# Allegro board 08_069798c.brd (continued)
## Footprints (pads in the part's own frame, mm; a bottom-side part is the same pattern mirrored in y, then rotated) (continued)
TSOT23_6
  rect 0.61x1.219 smd: 1(-0.95,-1.31) 2(0,-1.31) 3(0.95,-1.31) 4(0.95,1.31) 5(0,1.31) 6(-0.95,1.31)
TSOT-5
  rect 0.508x1.524 smd: 1(-0.95,-1.17) 2(0,-1.17) 3(0.95,-1.17) 4(0.95,1.17) 5(-0.95,1.17)
unnamed
  round 1.016 smd: (0,0)
YSML79W63H31_A
  rect 0.889x0.762 smd: 1(-0.65,-0.525) 2(0.65,-0.525) 3(0.65,0.525) 4(-0.65,0.525)

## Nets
5V_SUPP: C6.1 C57.1 C58.1 C61.1 C93.1 JP4.1 JP6.1 JP19.3 JP20.1 JP23.3 JP24.2(COM) R1.2(N2) R28.2(N2) R51.2(N2) R54.2(N2) R91.1 R113.2(N2) R116.2(N2) R117.1 R118.1 U25.2 U36.2 UNK5V_VDD.1
+3V3AFMC: C64.1 P3.D32 U18.8
+3V3CLK: C66.1 C104.2(N2) C124.1 C126.1 C128.1 C130.1 C131.1 C132.1 C133.1 C134.1 C143.1 R61.1 R98.2(N2) U30.6 U30.10 U30.26 U30.28 U30.32 U31.5(VOUT) Y1.4(VDD)
+3V3FMC: A2.6 A3.6 A4.6 C2.1 C44.1 C47.1 C48.1 C63.1 P3.C39 P3.D36 P3.D38 P3.D40 R19.1 R20.1 R35.1 R43.1 R44.1 R45.1 R77.1 R92.1 R93.1 R94.1 R133.1 U9.1 U9.5 U29.5
+3V3VCCO: C105.2(N2) C135.1 C139.1 C144.1 L3.2(N2) L4.2(N2) R100.2(N2) U30.16 U30.17(VVCO2) U32.5(VOUT)
+12V0FMC: C4.1 C5.1 C24.1 C25.1 C26.1 JP23.1 P3.C35 P3.C37 U37.1 U37.2 U37.3 U37.7 U38.1(VIN)
AGND: A2.2 A3.2 A4.2 A5.5 C1.2(N2) C2.2(N2) C3.2(N2) C4.2(N2) C5.2(N2) C6.2(N2) C9.2(N2) C10.2(N2) C11.2(N2) C12.2(N2) C13.2(N2) C14.2(N2) C15.1 C16.2(N2) C19.2(N2) C20.2(N2) C21.2(N2) C22.2(N2) C23.2(N2) C24.2(N2) C25.2(N2) C28.2(N2) C29.1 C30.2(N2) C31.1 C32.2(N2) C33.2(N2) C34.2(N2) C36.1 C37.2(N2) C39.1 C40.2(N2) C41.2(N2) C42.2(N2) C43.2(N2) C44.2(N2) C45.2(N2) C46.2(N2) C47.2(N2) C48.2(N2) C49.2(N2) C50.2(N2) C51.2(N2) C52.2(N2) C53.2(N2) C54.2(N2) C55.2(N2) C56.2(N2) C57.2(N2) C58.2(N2) C59.2(N2) C61.2(N2) C62.2(N2) C63.2(N2) C64.2(N2) C66.2(N2) C67.2(N2) C68.2(N2) C69.2(N2) C70.2(N2) C71.2(N2) C72.2(N2) C73.2(N2) C74.2(N2) C76.2(N2) C77.2(N2) C78.2(N2) C79.2(N2) C80.2(N2) C81.2(N2) C82.2(N2) C83.2(N2) C84.2(N2) C85.2(N2) C86.2(N2) C87.2(N2) C88.2(N2) C89.1 C90.2(N2) C91.1 C92.2(N2) C93.2(N2) C94.1 C95.2(N2) C96.1 C97.2(N2) C98.1 C99.2(N2) C100.1 C101.2(N2) C102.2(N2) C109.2(N2) C118.2(N2) C119.2(N2) C120.2(N2) C121.2(N2) C122.2(N2) C123.2(N2) C124.2(N2) C125.2(N2) C126.2(N2) C127.2(N2) C128.2(N2) C129.2(N2) C130.2(N2) C131.2(N2) C132.2(N2) C133.2(N2) C134.2(N2) C135.2(N2) C136.2(N2) C139.2(N2) C140.2(N2) C141.2(N2) C142.2(N2) C143.2(N2) C144.2(N2) CLKIN.2 CLKIN.3 CLKIN.4 CLKIN.5(SH4) CNVEN.C DS1.C INM.2 INM.3 INM.4(SH3) INP.2 INP.3 INP.4(SH3) JP3.3 JP5.3 JP7.1 JP10.3 JP11.3 JP12.3 JP13.3 JP14.1 JP15.1 JP16.1 JP21.1 JP22.1 L1.2(N2) P1.2 P1.6 P2.2 P2.6 P3.C1 P3.C4 P3.C5 P3.C8 P3.C9 P3.C12 P3.C13 P3.C16 P3.C17 P3.C20 P3.C21 P3.C24 P3.C25 P3.C28 P3.C29 P3.C32 P3.C33 P3.C36 P3.C38 P3.C40 P3.D2 P3.D3 P3.D6 P3.D7 P3.D10 P3.D13 P3.D16 P3.D19 P3.D22 P3.D25 P3.D28 P3.D37 P3.D39 P3.G1 P3.G4 P3.G5 P3.G8 P3.G11 P3.G14 P3.G17 P3.G20 P3.G23 P3.G26 P3.G29 P3.G32 P3.G35 P3.G38 P3.G40 P3.H2 P3.H3 P3.H6 P3.H9 P3.H12 P3.H15 P3.H18 P3.H21 P3.H24 P3.H27 P3.H30 P3.H33 P3.H36 P3.H39 P4.2 P4.4 P4.6(N6) P5.1 P7.11 P7.12(N6) P8.2 P8.4(N4) P11.2(N2) P12.1 R2.2(N2) R3.2(N2) R38.1 R42.2(N2) R62.2(N2) R67.1 R73.2(N2) R75.2(N2) R86.2(N2) R95.2(N2) R96.2(N2) R97.2(N2) R99.1 R101.1 R107.2(N2) R108.2(N2) R112.2(N2) R121.2(N2) R124.2(N2) R126.2(N2) R130.2(N2) R131.2(N2) R134.2(N2) R135.2(N2) R136.2(N2) R139.2(N2) R148.2(N2) R152.2(N2) S1.1A S1.2A S1.3A T1.4 TP1.1(N1) TP2.1(N1) TP3.1(N1) TP4.1(N1) U4.2 U4.5 U5.2 U5.5 U6.2 U6.5 U7.2 U7.5 U8.B1 U8.B2 U8.B6 U8.C1 U8.C2 U8.C3 U8.C4 U8.C5 U8.D3 U8.D4 U8.D5 U8.E3 U8.E4 U8.E5 U8.F5 U8.F6 U8.G5 U9.2 U11.2 U12.2 U13.2 U14.2 U15.2 U16.2 U17.2 U18.3 U18.4 U18.7(WC_N) U19.1 U19.4 U20.PAD U21.9 U21.PAD U23.3 U24.3 U25.3 U25.4 U25.5 U25.8 U26.3 U27.3 U28.3 U29.1 U29.3 U30.8 U30.9 U30.11 U30.18 U30.21 U30.27 U30.31 U30.PAD U31.2 U32.2 U33.9 U33.PAD U34.9 U34.PAD U35.9 U35.PAD U36.4 U37.9 U37.PAD U38.9 Y1.2
AVDD11: A2.3(VIN) P9.1 R36.1 U8.A1 U8.A2
DVDD11: R36.2(N2) R37.1 U8.A3
V11_OK: A2.4 A3.4 R47.2(N2) U24.1
VDD_REFBUF: C9.1 R1.1 U39.6
VDDAFE_U1: C88.1 R113.1 U1.6
VDDAFE_U2: C90.1 R28.1 U2.6
VDDCR11: P9.2(N2) R23.2(N2) R90.2(N2) VDD_11.1(N1)
VDDDRV_A1: A1.7(VS_POS) C95.1 R117.2(N2)
VDDDRV_A6: A6.7(VS_POS) C97.1 R118.2(N2)
VDDIO11: C1.1 C52.1 C53.1 C54.1 C59.1 C74.1 C76.1 C77.1 C78.1 C84.1 C85.1 IOVDD.1(N1) P10.1 R22.2(N2) R83.2(N2) U4.6(VCCB) U5.6(VCCB) U6.6(VCCB) U7.6(VCCB) U11.6(VCCB) U12.6(VCCB) U13.6(VCCB) U14.6(VCCB) U15.6(VCCB) U16.6(VCCB) U17.6(VCCB)
VDDLDO: C99.1 P6.2(N2) U8.B3 VDDLDO.1(N1)
VINN: INM.1 P1.7(N7) R3.1 R6.1 R106.1 TINM.1(N1)
VINP: INP.1 P1.1 R2.1 R4.1 R52.1 TINP.1(N1)
VSS_REFBUF: R152.1 U39.2
VSSAFE: C94.2(N2) JP3.1 JP5.1 JP19.1 JP20.3 JP21.3 JP22.3 JP25.2(COM) R26.2(N2) R27.2(N2) R115.2(N2) R128.1 R129.1 S1.4A U3.PAD VSS2V5.1(N1)
VSSAFE_U1: C89.2(N2) R26.1 U1.2(V-)
VSSAFE_U2: C91.2(N2) R27.1 U2.2(V-)
VSSDRV_A1: A1.4 A1.5 C96.2(N2) R128.2(N2)
VSSDRV_A6: A6.4 A6.5 C98.2(N2) R129.2(N2)
AD9508_RESET_N: U9.4 U20.18
AD9508_S4: R72.2(N2) R73.1 U20.9
AD9508_S5: R74.2(N2) R75.1 U20.10
AD9508_SYNC: P3.C10 U20.20 U29.2
ADCIN+: R31.1 R32.1 R70.2(N2)
ADCIN-: R76.2(N2) R88.1 R89.1
ADF435X_LOCK: P3.C23 R123.2(N2)
AUXIN+: C38.2(N2) C39.2(N2) R31.2(N2) U8.D2
AUXIN-: C38.1 C40.1 R89.2(N2) U8.E2
CLK25M: U30.29 Y1.3
CLK_N: P3.D9 RTCLK.1 U8.A7 U20.17
CLK_P: P3.D8 RTCLK.2(N2) U8.B7 U20.16
CLK_PWR_SRC: C141.1 C142.1 JP23.2(COM) U31.1 U32.1
CLK_SRCM: C138.2(N2) R68.2(N2) R69.1 U20.22
CLK_SRCP: C137.2(N2) R65.2(N2) R69.2(N2) U20.21
CLKCOM: C121.1 C123.1 U30.23
CLKIN_AUX: C65.1 CLKIN.1 R62.1
CMSRC: JP8.2(COM) U8.G2
CNV_N: R38.2(N2) R40.1 RTCNV.2(N2) U8.A5 U20.12
CNV_P: R39.1 RTCNV.1 U8.A4 U20.11
CPO: C125.1 R120.2(N2) U30.7
CS1_0: P3.C19 U20.1
CS1_1: P3.C22 U30.3
CS_N_SRC: P3.G12 R109.1 U11.3
CSB: R109.2(N2) U8.G1 U11.4
DA_N: JP11.1 P3.H8 U8.D7
DA_P: JP10.1 P3.H7 U8.C7
DB_N: JP13.1 P3.G10 U8.D6
DB_P: JP12.1 P3.G9 U8.C6
DCO_N: P3.H5 U8.B4
DCO_P: P3.H4 U8.B5
DOA: JP10.2(COM) U4.4
DOA_FMC: P3.D20 U4.3
DOB: JP11.2(COM) U5.4
DOB_FMC: P3.D21 U5.3
DOC: JP12.2(COM) U6.4
DOC_FMC: P3.G18 U6.3
DOD: JP13.2(COM) U7.4
DOD_FMC: P3.G19 U7.3
EC0: C70.1 U20.5
EC1: C69.1 U20.14
EN1V1: P5.2(N2) R20.2(N2) U35.4
EN_AFE: P2.4 U3.12 U23.4(Y) U25.1 U26.2 U27.2 U28.1 U36.3 U39.5
EN_PSU: P3.H19 R133.2(N2) U19.3 U38.2
EN_V33: U21.4 U24.4(Y)
EN_VDDLDO: P12.2(N2) R19.2(N2) U33.4
ENS1N: U2.5 U27.4(Y)
ENS1P: U1.5 U26.4(Y)
ENS3: A1.8 A6.8 U28.4(Y)
ENVIO: R35.2(N2) U34.4
EXT_5V: C101.1 JP24.1 P8.1
EXT_M2V5: C34.1 JP25.1 P8.3
EXT_VDD1V1: P4.5 R81.1 R90.1
EXT_VDD3V3: P11.1 R34.1 R82.1
EXT_VDDLDO: P4.3 R80.1 R84.1
EXT_VIO1V1: P4.1 R79.1 R83.1
FDA5: JP4.2(COM) R125.1 U3.5
FDA8: JP6.2(COM) R127.1 U3.8
FDA13: JP5.2(COM) R126.1 U3.13
FDA16: JP3.2(COM) R124.1 U3.16
FDA_OB_N: R102.1 U3.11
FDA_OB_P: R103.1 U3.10
FDA_ON: C75.1 JP15.3 JP17.1 P2.1 R33.2(N2) R102.2(N2)
FDA_OP: C75.2(N2) JP16.3 JP18.1 P2.7(N7) R18.2(N2) R103.2(N2)
FFB: C122.1 R119.2(N2) R122.1
FMC_VADJ: C3.1 C49.1 C50.1 C51.1 C55.1 C56.1 C62.1 C68.1 C71.1 C72.1 C73.1 C80.1 C81.1 C82.1 C83.1 P3.G39 P3.H40 P7.1 R16.1 R46.1 R47.1 R53.1 R55.1 R56.1 R71.1 R72.1 R74.1 U4.1 U5.1 U6.1 U7.1 U9.6(VCCB) U11.1 U11.5 U12.1 U12.5 U13.1 U13.5 U14.1 U15.1 U16.1 U17.1 U20.6 U20.13(VDD_2) U23.5 U24.5 U26.5 U27.5 U28.5
FPGACLK_N: P3.G3 U20.3
FPGACLK_P: P3.G2 U20.2
GA0: P3.C34 U18.2
GA1: P3.D35 U18.1
GP0_DIR: P3.H16 U14.5
GP1_DIR: P3.C15 U15.5
GP2_DIR: P3.G15 U16.5
GP3_DIR: P3.H17 U17.5
GPIO0: U8.G7 U14.4
GPIO0_FMC: P3.H13 U14.3
GPIO1: U8.E6 U15.4
GPIO1_FMC: P3.C11 U15.3
GPIO2: U8.F1 U16.4
GPIO2_FMC: P3.D14 U16.3
GPIO3: U8.F2 U17.4
GPIO3_FMC: P3.D15 U17.3
IN+: C35.2(N2) C36.2(N2) R32.2(N2) U8.D1
IN-: C35.1 C37.1 R88.2(N2) U8.E1
IOVDD: A3.3(VIN) P10.2(N2) R37.2(N2) U8.A6
LDO_IN_VDD1V1: C13.1 R81.2(N2) R93.2(N2) U35.1 U35.2 U35.3 U35.7
LDO_IN_VDD3V3: C10.1 R34.2(N2) R91.2(N2) U21.1 U21.2 U21.3 U21.7
LDO_IN_VDDLDO: C11.1 R80.2(N2) R92.2(N2) U33.1 U33.2 U33.3 U33.7
LDO_IN_VIO1V1: C12.1 R79.2(N2) R94.2(N2) U34.1 U34.2 U34.3 U34.7
NEG_5V0: C26.2(N2) C27.2(N2) C29.2(N2) C118.1 R137.2(N2) R138.2(N2) U19.2 U38.12 U38.PAD
OSC_EN: P3.G16 R61.2(N2) U30.4 Y1.1
OUT_VDDLDO: P6.1 R21.2(N2) R84.2(N2)
P1N: R55.2(N2) S1.2B U27.1
P1P: R53.2(N2) S1.1B(N8) U26.1
P1S1: JP19.2(COM) P1.3
P1S2: JP20.2(COM) P1.5
P3: R56.2(N2) S1.3B U28.2
PAD_A1: A1.PAD JP21.2(COM)
PAD_A6: A6.PAD JP22.2(COM)
PBIO<0>: P3.H23 P7.2
PBIO<1>: P3.G21 P7.3
PBIO<2>: P3.G22 P7.4
PBIO<3>: P3.H25 P7.5
PBIO<4>: P3.H26 P7.6
PBIO<5>: P3.G24 P7.7
PBIO<6>: P3.G25 P7.8
PBIO<7>: P3.D23 P7.9
PBIO<8>: P3.D24 P7.10
PD_V33B: P3.H22 R16.2(N2) U23.2 U24.2
PG_C2M: A2.1 A4.1 P3.D1 R24.1 R43.2(N2) R44.2(N2) U31.3 U32.3
PMSEL: JP4.3 R54.1 R125.2(N2) S1.4B
PWRGD: A4.4 P3.H20 R46.2(N2) R85.1 U9.3 U23.1
REF: C41.1 C42.1 C43.1 JP2.2(COM) JP6.3 R127.2(N2) REF.1(N1) U8.F4 U8.G4
REF3P: C30.1 R147.1 U25.6(VOUT_S) U25.7
REF3S: R146.1 U36.6(VOUT)
REFBUF_IN: JP1.3 R148.1 R149.1
REFBUF_OUT: JP2.1 R151.2(N2)
REFCLK: C127.1 C129.1 U30.24
S1_OM: C32.1 R11.1 R18.1 R106.2(N2) R114.2(N2)
S1_OP: C31.2(N2) R10.1 R33.1 R52.2(N2) R66.2(N2)
SCK: R111.2(N2) U8.E7 U13.4
SCL: P3.C30 U18.6
SCLK1: P3.D18 U20.19 U30.1
SCLK_SRC: P3.H14 R111.1 U13.3
SDA: P3.C31 U18.5
SDI: R110.2(N2) U8.F7(SDI) U12.4
SDIN1: P3.C18 U20.24 U30.2
SDIO_SRC: P3.G13 R110.1 U12.3
SDO_1: P3.D17 U20.4
SNS33: R41.1 R82.2(N2) R132.2(N2) U8.F3 U8.G3 VDD33.1(N1)
TMPC: C136.1 C140.1 U30.19
UNNAMED_4_CMOSNC7SZ125_I71_Y: R60.1 U29.4(Y)
UNNAMED_4_CN160PCDGHV2_I72_TDI: P3.D30 P3.D31
UNNAMED_4_CN160PCDGHV2_I97_LA00NCC: P3.G7 R40.2(N2)
UNNAMED_4_CN160PCDGHV2_I97_LA00PCC: P3.G6 R39.2(N2)
UNNAMED_4_DIOLED_I76_P: CNVEN.A(P) R60.2(N2)
UNNAMED_5_ADM108X_I2_ENIN: A3.1 R45.2(N2)
UNNAMED_5_ADM108X_I19_VIN: A4.3(VIN) R41.2(N2) R42.1
UNNAMED_5_DIOLED_I115_P: DS1.A(P) R85.2(N2)
UNNAMED_7_AD9508_I87_INSEL: R71.2(N2) U20.23
UNNAMED_7_ADF435X_I58_MUXOUT: R123.1 U30.30
UNNAMED_7_ADF435X_I58_RFOUTA: C138.1 L4.1 U30.13
UNNAMED_7_ADF435X_I58_RFOUTA_1: C137.1 L3.1 U30.12
UNNAMED_7_ADF435X_I58_RSET: R121.1 U30.22
UNNAMED_7_ADF435X_I58_SW: R122.2(N2) U30.5
UNNAMED_7_ADP7118V2_I90_SENSE: C105.1 R100.1 R101.2(N2) U32.4
UNNAMED_7_ADP7118V2_I95_SENSE: C104.1 R98.1 R99.2(N2) U31.4
UNNAMED_7_CAP_I6_N2: C65.2(N2) T1.5(N4)
UNNAMED_7_RES_I8_N1: R64.2(N2) R68.1 T1.3
UNNAMED_7_RES_I10_N1: R63.1 R65.1 T1.1
UNNAMED_7_RES_I10_N2: R63.2(N2) R64.1
UNNAMED_8_ADA4899_I108_FEEDBACK: A1.1 R17.2(N2)
UNNAMED_8_ADA4899_I108_INV: A1.2 R17.1
UNNAMED_8_ADA4899_I108_NINV: A1.3 R58.2(N2)
UNNAMED_8_ADA4899_I108_VOUT: A1.6 R105.1
UNNAMED_8_ADA4899_I113_FEEDBACK: A6.1 R57.2(N2)
UNNAMED_8_ADA4899_I113_INV: A6.2 R57.1
UNNAMED_8_ADA4899_I113_NINV: A6.3 R59.2(N2)
UNNAMED_8_ADA4899_I113_VOUT: A6.6 R104.1
UNNAMED_8_ADA49451_I81_: C18.2(N2) R15.2(N2) U3.4
UNNAMED_8_ADA49451_I81__1: C17.2(N2) R14.2(N2) U3.1
UNNAMED_8_ADA49451_I81__2: C18.1 R13.2(N2) U3.3
UNNAMED_8_ADA49451_I81__3: C17.1 R12.2(N2) U3.2
UNNAMED_8_ADA49451_I81__4: C19.1 R115.1 U3.14 U3.15
UNNAMED_8_ADA49451_I81__5: C20.1 R116.1 U3.6 U3.7
UNNAMED_8_ADLT6236_I15_: C79.1 R6.2(N2) U2.3
UNNAMED_8_ADLT6236_I15__1: C8.1 R7.2(N2) R9.1 U2.4
UNNAMED_8_ADLT6236_I15_OUT: C8.2(N2) R9.2(N2) R114.1 U2.1
UNNAMED_8_ADLT6236_I33_: C67.1 R4.2(N2) U1.3
UNNAMED_8_ADLT6236_I33__1: C7.1 R5.2(N2) R8.1 U1.4
UNNAMED_8_ADLT6236_I33_OUT: C7.2(N2) R8.2(N2) R66.1 U1.1
UNNAMED_8_CAP_I54_N1: C16.1 C103.2(N2) R11.2(N2) R13.1 R15.1
UNNAMED_8_CAP_I57_N2: C15.2(N2) C103.1 R10.2(N2) R12.1 R14.1
UNNAMED_8_CAP_I93_N1: C109.1 JP15.2(COM) R58.1
UNNAMED_8_CAP_I115_N1: C92.1 JP16.2(COM) R59.1
UNNAMED_8_OFFPAGE_I160_A: R30.2(N2)
UNNAMED_8_RES_I10_N1: R5.1 R29.2(N2)
UNNAMED_8_RES_I20_N1: R7.1 R78.1
UNNAMED_8_RES_I20_N2: JP14.2(COM) R78.2(N2)
UNNAMED_8_RES_I163_N1: JP17.2(COM) R70.1
UNNAMED_8_RES_I164_N1: JP18.2(COM) R76.1
UNNAMED_8_RES_I185_N2: JP17.3 R105.2(N2)
UNNAMED_8_RES_I186_N2: JP18.3 R104.2(N2)
UNNAMED_8_RES_I219_N1: JP7.2(COM) R29.1
UNNAMED_11_CAP_I205_N1: C14.1 R132.1 U21.10 U21.11 U21.12
UNNAMED_11_CAP_I213_N1: C21.1 R21.1 U33.10 U33.11 U33.12
UNNAMED_11_CAP_I221_N1: C23.1 R23.1 U35.10 U35.11 U35.12
UNNAMED_11_CAP_I227_N1: C22.1 R22.1 U34.10 U34.11 U34.12
UNNAMED_11_LINLT3045_I202_ILIM: R108.1 U21.6
UNNAMED_11_LINLT3045_I202_SET: C46.1 R95.1 U21.8(SET)
UNNAMED_11_LINLT3045_I215_ILIM: R112.1 U33.6
UNNAMED_11_LINLT3045_I215_SET: C86.1 R96.1 U33.8(SET)
UNNAMED_11_LINLT3045_I220_ILIM: R131.1 U35.6
UNNAMED_11_LINLT3045_I220_SET: C87.1 R107.1 U35.8(SET)
UNNAMED_11_LINLT3045_I229_ILIM: R130.1 U34.6
UNNAMED_11_LINLT3045_I229_SET: C45.1 R97.1 U34.8(SET)
UNNAMED_12_ADLT8604_I100_FB: R138.1 R139.1 U38.5
UNNAMED_12_ADLT8604_I100_RT: R137.1 U38.8
UNNAMED_12_ADLT8604_I100_SW: L1.1 U38.10
UNNAMED_12_ADLT8604_I100_SYNC: R136.1 U38.7
UNNAMED_12_ADLT8604_I100_TR: C27.1 U38.6
UNNAMED_12_ADP7182V3_I25_VOUT: C119.1 JP25.3 U19.5(VOUT)
UNNAMED_12_CAP_I88_N1: C28.1 JP24.3 U37.10 U37.11 U37.12
UNNAMED_12_LINLT3045_I87_EN: R24.2(N2) R77.2(N2) U37.4
UNNAMED_12_LINLT3045_I87_ILIM: R135.1 U37.6
UNNAMED_12_LINLT3045_I87_SET: C102.1 R134.1 U37.8(SET)
UNNAMED_13_ADA48072_I2_INV: A5.6 A5.7
UNNAMED_13_ADA48072_I13_INV: A5.2 C60.1 R49.1
UNNAMED_13_ADA48072_I13_NINV: A5.3 R48.2(N2)
UNNAMED_13_ADA48072_I13_OUT: A5.1 C60.2(N2) R50.1
UNNAMED_13_ADA48072_I20_VS: A5.8 R51.1
UNNAMED_13_ADA48072_I20_VS_1: A5.4(VS-) R67.2(N2)
UNNAMED_13_ADA48971_I40_: R149.2(N2) U39.3
UNNAMED_13_ADA48971_I40__1: R150.1 U39.4
UNNAMED_13_ADA48971_I40_OUT: R150.2(N2) R151.1 U39.1(OUT)
UNNAMED_13_RES_I12_N1: JP8.3 R48.1 R86.1
UNNAMED_13_RES_I17_N2: R49.2(N2) R50.2(N2) R87.1
UNNAMED_13_RES_I28_N2: JP9.3 R87.2(N2)
UNNAMED_13_RES_I29_N2: JP1.2(COM) R146.2(N2) R147.2(N2)
UNNAMED_13_RESJMPR3P_I53_B: JP1.1 JP2.3
UNNAMED_13_RESJMPRSHRT3P_I11_A: JP8.1 JP9.1
VOCM: C33.1 C100.2(N2) JP7.3 JP9.2(COM) JP14.3 P1.4 R30.1 U3.9(VOCM) VOCM.1(N1)
VTIN: C120.1 R119.1 R120.1 U30.20

Pads without a net: A2 5; A3 5; A4 5; P2 3 5; P3 C2 C3 C6 C7 C14 C26 C27 D4 D5 D11 D12 D26 D27 D29 D33 D34 G27 G28 G30 G31 G33 G34 G36 G37 H1 H10 H11 H28 H29 H31 H32 H34 H35 H37 H38; T1 2; U8 G6; U20 7 8 15; U21 5; U30 14 15 25; U33 5; U34 5; U35 5; U36 1 5 7 8; U37 5; U38 3 4 11

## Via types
v1: diameter 0.508, hole 0.254, TOP to BOTTOM, 1140 vias
v2: diameter 0.457, hole 0.152, TOP to BOTTOM, 33 vias
v3: diameter 0.711, hole 0.356, TOP to BOTTOM, 36 vias

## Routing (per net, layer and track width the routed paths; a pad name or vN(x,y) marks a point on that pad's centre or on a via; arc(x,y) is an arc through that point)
5V_SUPP: length 48.1
  TOP w0.305: 56.19,18.72 R91.1
  TOP w0.508: v2(88.82,51.17) 88.82,50.53 JP23.3 ; v1(51.54,4.3) 50.68,4.3 C61.1 R51.2 ; R54.2 v1(23.6,12.89)
  L3_PRIMARY_POWER w0.508: UNK5V_VDD.1 27.68,22.1 ; UNK5V_VDD.1 27.68,20.42 ; UNK5V_VDD.1 26,20.42 ; UNK5V_VDD.1 26,22.1
  BOTTOM w0.305: v2(88.82,51.17) 86.85,49.2 82.6,49.2 81.64,48.25 80.63,48.25 79.8,47.42 76.94,47.42 75.93,46.4 66.15,46.4 64.56,44.82 60.94,44.82 v1(58.99,42.86)
  BOTTOM w0.508: JP24.2 28.27,18.56 v1(28.27,19.19) ; JP20.1 v1(13.07,31.38) ; JP19.3 v1(13.07,34.66) ; JP6.1 v1(38.93,26.4) ; JP4.1 v1(33.88,26.4)
  vias: v1(22.73,36.89) v1(22.73,36.26) v1(22.74,21.53) v1(22.74,20.89) v1(23.36,36.89) v1(23.35,36.24) v1(23.38,21.53) v1(23.36,20.88) v1(35.62,26.86) v1(35.62,26.35) v1(36.13,26.86) v1(36.13,26.35) v1(57.02,19.05) v1(57.02,18.35) v1(57.65,19.05) v1(57.65,18.35) v1(58.48,42.86) v1(58.48,42.35) v1(58.48,28.58) v1(58.48,28.07) v1(58.99,42.35) v1(58.99,28.58) v1(58.99,28.07) v1(63.69,18.25) v1(63.69,17.74) v1(63.69,11.46) v1(63.69,10.95) v1(64.19,18.25) v1(64.19,17.74) v1(64.19,11.46) v1(64.19,10.95) v1(72.7,22.89) v1(72.7,22.38) v1(73.21,22.89) v1(73.21,22.38)
+3V3AFMC: length 11
  TOP w0.254: U18.8 91.5,18.67 90.26,18.67 C64.1
  TOP w0.508: U18.8 91.75,17.78 92.26,17.27 96.36,17.27 96.87,17.78 v1(96.87,19.54)
  BOTTOM w0.508: P3.D32 v1(96.87,19.54)
+3V3CLK: length 10.8
  TOP w0.178: v1(61.5,51.48) 61.2,51.79 U30.6 ; U30.28 57.99,55.69 57.59,55.69 57.26,56.02 ; U30.10 63.23,54.19 63.25,54.17 63.53,54.17 63.81,53.88 63.81,53.51 64.39,52.93 C126.1 64.39,52.27 64.41,52.25 C128.1 64.41,51.63 64.51,51.53 v1(64.51,51.03)
  BOTTOM w0.178: v1(64.51,51.03) v1(64.51,50.42) 63.84,50.42 C66.1 C132.1 62.22,50.77 v1(61.5,51.48)
  vias: v1(54.6,56.58) v1(54.6,56.07) v1(54.73,52.51) v1(54.73,51.94) v1(58.08,62.6) v1(59.14,63.44) v1(59.16,62.6) v1(60.24,63.42) v1(60.24,62.6) v1(79.75,57.6) v1(79.74,57.01) v1(79.74,56.44)
+3V3FMC: length 68.1
  TOP w0.254: v1(83.61,16.88) 83.61,17.38 81.07,19.92 79.99,19.92 78.91,21 78.91,28.69 78.09,29.51 78.09,31.86 78.85,32.62 78.85,33 78.86,33.02 78.86,34.9 77.52,36.24 77.52,41.77 C2.1 ; v1(101.09,45.43) 101.09,45.43 C63.1 101.09,46.04 U29.5 ; A3.6 80.32,11.93 80.41,11.84 C48.1 ; A2.6 C47.1
  TOP w0.305: v1(49.26,3.22) 49.26,7.54 v1(46.59,10.21) ; v1(43.48,12.24) 43.48,13.96 v1(42.34,15.1) ; C2.1 U9.1
  TOP w0.381: A4.6 C44.1 ; U9.5 78.29,44.51 77.64,43.86 U9.1
  TOP w0.508: v1(81.71,4.56) 80.86,4.56 C44.1 ; R45.1 C48.1 80.44,11.23 v1(80.44,10.46) ; 13.76,49.59 R20.1 13.14,50.16 ; 27.17,49.97 R19.1 27.8,49.4 ; R43.1 82.73,3.54 v1(83.55,3.54) ; v1(76.37,10.53) 76.37,11.25 C47.1 R44.1 ; 41.77,49.33 R35.1 41.14,49.9
  L3_PRIMARY_POWER w0.305: v1(43.48,12.24) 44.24,11.48 45.32,11.48 v1(46.59,10.21)
  BOTTOM w0.254: v1(83.61,16.88) R133.1 ; R77.1 41.57,15.1 v1(42.34,15.1)
  BOTTOM w0.508: P3.C39 v1(98.14,10.65) ; P3.D40 v1(96.87,9.38) ; P3.D36 v1(96.87,14.46) ; P3.D38 v1(96.87,11.92)
  vias: v1(11.81,50.23) v1(11.81,49.53) v1(12.44,50.23) v1(12.44,49.53) v1(25.84,50.16) v1(25.84,49.47) v1(26.47,50.16) v1(26.47,49.47) v1(39.62,50.29) v1(39.62,49.59) v1(40.25,50.29) v1(40.25,49.59)
+3V3VCCO: length 1.6
  TOP w0.508: L4.2 v1(65.32,56.88) ; L3.2 v1(65.34,54)
  vias: v1(63.69,59.88) v1(64.26,59.88) v1(79.67,51.42) v1(79.67,50.85) v1(79.67,50.28)
+12V0FMC: length 7.2
  TOP w0.508: v1(87.29,55.17) 87.29,53.16 87.42,53.03 JP23.1
  BOTTOM w0.254: v1(35.8,13.64) 35.8,14.48 U37.7 ; U38.1 83.44,19.02 C26.1
  BOTTOM w0.508: P3.C35 v1(98.14,15.73) ; P3.C37 v1(98.14,13.19)
  vias: v1(45.84,16.07) v1(45.84,15.3) v1(45.84,14.54) v1(46.6,16.07) v1(46.6,15.3) v1(46.6,14.54) v1(47.37,16.07) v1(47.37,15.3) v1(47.37,14.54) v1(84.64,17.53) v1(84.64,16.83) v1(85.28,18.35) v1(85.28,17.53) v1(85.28,16.83) v1(85.9,19.16) v1(85.91,18.35) v1(85.91,17.53) v1(85.91,16.83)
AGND: length 616.5
  TOP w0.203: 81.56,23.47 v1(81.56,24.12) ; 81.56,27.15 v1(81.56,27.79) ; 81.56,46.05 v1(81.56,46.69) ; v1(81.56,35.66) 81.56,35.02
  TOP w0.254: 74.03,5.43 v1(74.03,5.12) ; C140.2 62.73,60.18 62.73,59.94 ; 101.09,46.67 C63.2 101.09,47.28 v1(101.08,47.28) ; v1(99.37,49.91) 99.37,48.83 U29.1 ; R97.2 52.05,51.48 52.12,51.42 ; 50.46,15.99 50.59,16.11 C46.2 ; U24.3 v1(71.57,5.17) ; v1(15.17,14.9) 14.93,15.14 U26.3 ; U30.11 61.2,54.69 v1(60.45,55.44) ; U30.18 61.7,56.69 v1(60.45,55.44) ; v1(60.45,55.44) 60.2,55.69 ; 60.2,55.69 59.7,56.19 U30.27 ; 60.2,55.69 U30.21 ; v1(19.74,14.85) 19.5,15.09 U27.3 ; 78.79,5.76 78.82,5.73 C55.2 ; v1(62.9,53.08) U30.9 ; U23.3 v1(76.65,5.17) ; C121.2 57.74,59.94
  TOP w0.305: 38.08,51.23 38.12,51.19 38.12,50.93 ; U30.8 62.2,52.26 ; U30.31 57.02,54.19 v1(56.96,54.13)
  TOP w0.508: 37.51,63.93 38.4,64.82 ; 38.4,64.82 39.29,63.93 ; 38.4,64.82 39.29,65.7 ; 38.4,64.82 37.51,65.7 ; TP4.1 11.24,13.18 ; TP4.1 9.55,13.18 ; TP4.1 9.55,14.86 ; TP4.1 11.24,14.86 ; CLKIN.2 80.19,62.81 ; CLKIN.2 80.19,60.77 ; CLKIN.2 78.15,60.77 ; CLKIN.2 78.15,62.81 ; P1.2 10.41,38.99 ; P1.2 10.41,37.21 ; P1.2 8.64,38.99 ; P1.2 8.64,37.21 ; P7.11 4.36,4.11 ; P7.11 2.59,4.11 ; P7.11 4.36,2.34 ; P7.11 2.59,2.34 ; 32.43,63.93 33.32,64.82 ; 33.32,64.82 34.21,63.93 ; 33.32,64.82 34.21,65.7 ; 33.32,64.82 32.43,65.7 ; CLKIN.3 80.19,65.87 ; CLKIN.3 78.15,65.87 ; CLKIN.3 78.15,67.91 ; CLKIN.3 80.19,67.91 ; 5.13,2.34 P7.12 ; P7.12 6.9,4.11 ; P7.12 6.9,2.34 ; P7.12 5.13,4.11 ; TP3.1 51.18,66.1 ; TP3.1 49.5,66.1 ; TP3.1 51.18,64.42 ; TP3.1 49.5,64.42 ; TP1.1 78.12,23.53 ; TP1.1 76.43,25.21 ; TP1.1 78.12,25.21 ; TP1.1 76.43,23.53 ; 8.64,27.05 P1.6 ; P1.6 10.41,28.83 ; P1.6 8.64,28.83 ; P1.6 10.41,27.05 ; v1(61.5,50.45) 61.61,50.56 C125.2 C122.2 ; 83.25,62.81 CLKIN.5 ; CLKIN.5 85.29,62.81 ; CLKIN.5 83.25,60.77 ; CLKIN.5 85.29,60.77 ; 45.97,37.21 P2.2 45.97,38.99 ; C120.2 v1(65.53,48.59) ; R3.2 v1(6.98,28.22) ; R2.2 v1(6.98,37.82) ; TP2.1 7.87,53.5 ; TP2.1 6.19,53.5 ; TP2.1 6.19,55.18 ; TP2.1 7.87,55.18 ; CLKIN.4 85.29,65.87 ; CLKIN.4 83.25,67.91 ; CLKIN.4 83.25,65.87 ; CLKIN.4 85.29,67.91 ; 27.35,63.93 28.24,64.82 ; 28.24,64.82 29.13,63.93 ; 28.24,64.82 29.13,65.7 ; 28.24,64.82 27.35,65.7 ; U18.7 93.02,19.86 v1(93.6,20.44) ; v1(13.95,24.1) C79.2 ; P12.1 32.22,45.35 ; P12.1 29.98,45.35 ; P12.1 29.98,47.59 ; P12.1 32.22,47.59 ; P5.1 18.18,47.71 ; P5.1 18.18,45.48 ; P5.1 15.95,47.71 ; P5.1 15.95,45.48 ; C142.2 v1(82.27,49.85) ; U32.2 v1(86.1,52.58) ; 45.26,5.44 P11.2 ; P11.2 47.03,3.67 ; P11.2 45.26,3.67 ; P11.2 47.03,5.44 ; v1(95.56,15.75) U18.4 ; T1.4 v1(68.45,66.48) ; 30.48,5.17 P8.2 30.48,3.31 ; v1(13.95,39.34) C67.2 ; 37.43,3.31 P8.4 37.43,5.17 ; R62.2 v1(77.21,62.57) ; U31.2 v1(86.1,58.36) ; C141.2 v1(82.27,55.69) ; v1(94.29,15.88) U18.3
  L2_GND w0.508: 32.43,63.93 33.32,64.82 ; 33.32,64.82 34.21,65.7 ; 33.32,64.82 34.21,63.93 ; 33.32,64.82 32.43,65.7 ; 30.26,45.63 P12.1 ; P12.1 30.26,47.31 ; P12.1 31.94,47.31 ; P12.1 31.94,45.63 ; P2.6 45.97,28.83 ; P2.6 45.97,27.05 ; P2.6 44.19,28.83 ; P2.6 44.19,27.05 ; TP1.1 78.12,25.21 ; TP1.1 78.12,23.53 ; TP1.1 76.43,25.21 ; TP1.1 76.43,23.53 ; 37.51,63.93 38.4,64.82 ; 38.4,64.82 37.51,65.7 ; 38.4,64.82 39.29,63.93 ; 38.4,64.82 39.29,65.7 ; 78.15,67.91 CLKIN.3 ; CLKIN.3 80.19,67.91 ; CLKIN.3 80.19,65.87 ; CLKIN.3 78.15,65.87 ; 6.19,53.5 TP2.1 ; TP2.1 7.87,55.18 ; TP2.1 7.87,53.5 ; TP2.1 6.19,55.18 ; CLKIN.4 85.29,65.87 ; CLKIN.4 83.25,65.87 ; CLKIN.4 85.29,67.91 ; CLKIN.4 83.25,67.91 ; TP3.1 51.18,64.42 ; TP3.1 49.5,64.42 ; TP3.1 51.18,66.1 ; TP3.1 49.5,66.1 ; 83.25,60.77 CLKIN.5 ; CLKIN.5 85.29,60.77 ; CLKIN.5 83.25,62.81 ; CLKIN.5 85.29,62.81 ; 2.59,4.11 P7.11 ; P7.11 4.36,4.11 ; P7.11 2.59,2.34 ; P7.11 4.36,2.34 ; 8.64,37.21 P1.2 ; P1.2 10.41,38.99 ; P1.2 8.64,38.99 ; P1.2 10.41,37.21 ; 35.56,3.31 P8.4 ; P8.4 37.43,5.17 ; P8.4 37.43,3.31 ; P8.4 35.56,5.17 ; 44.19,37.21 P2.2 ; P2.2 44.19,38.99 ; P2.2 45.97,37.21 ; P2.2 45.97,38.99 ; 78.15,62.81 CLKIN.2 ; CLKIN.2 80.19,60.77 ; CLKIN.2 80.19,62.81 ; CLKIN.2 78.15,60.77 ; 30.48,5.17 P8.2 ; P8.2 32.35,3.31 ; P8.2 32.35,5.17 ; P8.2 30.48,3.31 ; 28.24,64.82 29.13,65.7 ; 28.24,64.82 29.13,63.93 ; 28.24,64.82 27.35,65.7 ; 28.24,64.82 27.35,63.93 ; 45.26,5.44 P11.2 ; P11.2 45.26,3.67 ; P11.2 47.03,3.67 ; P11.2 47.03,5.44 ; 9.55,13.18 TP4.1 ; TP4.1 9.55,14.86 ; TP4.1 11.24,13.18 ; TP4.1 11.24,14.86 ; P5.1 17.91,47.44 ; P5.1 16.22,45.75 ; P5.1 16.22,47.44 ; P5.1 17.91,45.75 ; P1.6 10.41,28.83 ; P1.6 8.64,28.83 ; P1.6 10.41,27.05 ; P1.6 8.64,27.05 ; 5.13,2.34 P7.12 ; P7.12 6.9,4.11 ; P7.12 5.13,4.11 ; P7.12 6.9,2.34
  L3_PRIMARY_POWER w0.508: P7.11 4.36,4.11 ; P7.11 2.59,4.11 ; P7.11 4.36,2.34 ; P7.11 2.59,2.34 ; 78.15,60.77 CLKIN.2 80.19,60.77 ; P7.12 6.9,4.11 ; P7.12 5.13,4.11 ; P7.12 6.9,2.34 ; P7.12 5.13,2.34
  L4_GND w0.508: 76.43,23.53 TP1.1 ; TP1.1 76.43,25.21 ; TP1.1 78.12,23.53 ; TP1.1 78.12,25.21 ; 30.26,47.31 P12.1 ; P12.1 31.94,47.31 ; P12.1 30.26,45.63 ; P12.1 31.94,45.63 ; CLKIN.3 80.19,67.91 ; CLKIN.3 78.15,65.87 ; CLKIN.3 78.15,67.91 ; CLKIN.3 80.19,65.87 ; TP3.1 51.18,64.42 ; TP3.1 49.5,66.1 ; TP3.1 49.5,64.42 ; TP3.1 51.18,66.1 ; 9.55,14.86 TP4.1 ; TP4.1 11.24,14.86 ; TP4.1 9.55,13.18 ; TP4.1 11.24,13.18 ; 16.22,45.75 P5.1 ; P5.1 17.91,45.75 ; P5.1 16.22,47.44 ; P5.1 17.91,47.44 ; P1.2 10.41,37.21 ; P1.2 8.64,38.99 ; P1.2 10.41,38.99 ; P1.2 8.64,37.21 ; 44.19,27.05 P2.6 ; P2.6 45.97,27.05 ; P2.6 44.19,28.83 ; P2.6 45.97,28.83 ; 44.19,37.21 P2.2 ; P2.2 45.97,37.21 ; P2.2 44.19,38.99 ; P2.2 45.97,38.99 ; P11.2 47.03,5.44 ; P11.2 45.26,3.67 ; P11.2 45.26,5.44 ; P11.2 47.03,3.67 ; 6.19,53.5 TP2.1 ; TP2.1 7.87,53.5 ; TP2.1 7.87,55.18 ; TP2.1 6.19,55.18 ; P7.12 6.9,4.11 ; P7.12 6.9,2.34 ; P7.12 5.13,2.34 ; P7.12 5.13,4.11 ; 37.51,63.93 38.4,64.82 ; 38.4,64.82 39.29,65.7 ; 38.4,64.82 39.29,63.93 ; 38.4,64.82 37.51,65.7 ; CLKIN.5 85.29,62.81 ; CLKIN.5 83.25,62.81 ; CLKIN.5 83.25,60.77 ; CLKIN.5 85.29,60.77 ; 83.25,67.91 CLKIN.4 ; CLKIN.4 85.29,67.91 ; CLKIN.4 83.25,65.87 ; CLKIN.4 85.29,65.87 ; P8.4 37.43,5.17 ; P8.4 35.56,3.31 ; P8.4 37.43,3.31 ; P8.4 35.56,5.17 ; 30.48,3.31 P8.2 ; P8.2 32.35,5.17 ; P8.2 30.48,5.17 ; P8.2 32.35,3.31 ; P7.11 4.36,2.34 ; P7.11 2.59,4.11 ; P7.11 2.59,2.34 ; P7.11 4.36,4.11 ; 78.15,62.81 CLKIN.2 ; CLKIN.2 80.19,60.77 ; CLKIN.2 78.15,60.77 ; CLKIN.2 80.19,62.81 ; 8.64,27.05 P1.6 ; P1.6 10.41,28.83 ; P1.6 8.64,28.83 ; P1.6 10.41,27.05 ; 27.35,65.7 28.24,64.82 ; 28.24,64.82 29.13,63.93 ; 28.24,64.82 29.13,65.7 ; 28.24,64.82 27.35,63.93 ; 33.32,64.82 34.21,63.93 ; 33.32,64.82 32.43,65.7 ; 33.32,64.82 34.21,65.7 ; 33.32,64.82 32.43,63.93
  L5_SECONDARY_POWER w0.508: 28.24,64.82 29.13,63.93 ; 28.24,64.82 27.35,65.7 ; 28.24,64.82 29.13,65.7 ; 28.24,64.82 27.35,63.93 ; TP2.1 7.87,53.5 ; TP2.1 6.19,53.5 ; TP2.1 7.87,55.18 ; TP2.1 6.19,55.18 ; 38.4,64.82 39.29,63.93 ; 38.4,64.82 37.51,63.93 ; 38.4,64.82 37.51,65.7 ; 38.4,64.82 39.29,65.7 ; CLKIN.5 85.29,62.81 ; CLKIN.5 85.29,60.77 ; CLKIN.5 83.25,60.77 ; CLKIN.5 83.25,62.81 ; CLKIN.3 80.19,65.87 ; CLKIN.3 78.15,65.87 ; CLKIN.3 78.15,67.91 ; CLKIN.3 80.19,67.91 ; 44.19,37.21 P2.2 ; P2.2 45.97,38.99 ; P2.2 45.97,37.21 ; P2.2 44.19,38.99 ; TP3.1 51.18,66.1 ; TP3.1 51.18,64.42 ; TP3.1 49.5,66.1 ; TP3.1 49.5,64.42 ; 8.64,38.99 P1.2 ; P1.2 10.41,38.99 ; P1.2 8.64,37.21 ; 80.19,62.81 CLKIN.2 78.15,62.81 ; 32.43,65.7 33.32,64.82 ; 33.32,64.82 34.21,63.93 ; 33.32,64.82 32.43,63.93 ; 33.32,64.82 34.21,65.7 ; P5.1 17.91,45.75 ; P5.1 16.22,45.75 ; P5.1 17.91,47.44 ; P5.1 16.22,47.44 ; 83.25,67.91 CLKIN.4 ; CLKIN.4 85.29,67.91 ; CLKIN.4 85.29,65.87 ; CLKIN.4 83.25,65.87 ; 76.43,23.53 TP1.1 76.43,25.21 ; 44.19,28.83 P2.6 ; P2.6 45.97,28.83 ; P2.6 45.97,27.05 ; 8.64,27.05 P1.6 ; P1.6 10.41,27.05 ; P1.6 8.64,28.83
  BOTTOM w0.254: U38.9 79.68,18.52 v1(79.55,18.65) ; R134.2 31.8,15.29 31.67,15.16 ; C102.2 31.73,13.7 31.67,13.64
  BOTTOM w0.381: C43.2 70.66,29.89 v1(70.78,30.02)
  BOTTOM w0.508: 30.48,3.31 P8.2 ; P8.2 32.35,5.17 ; P8.2 30.48,5.17 ; P8.2 32.35,3.31 ; v1(93.34,39.24) 93.24,39.14 P3.G17 ; 32.43,63.93 33.32,64.82 ; 33.32,64.82 34.21,65.7 ; 33.32,64.82 34.21,63.93 ; 33.32,64.82 32.43,65.7 ; P3.H39 v1(90.7,10.65) ; P3.C38 v1(98.14,11.92) ; P3.H15 v1(90.7,42.23) ; P3.H27 v1(90.7,25.89) ; P3.H3 90.7,57.47 v1(90.7,57.64) P3.H2 ; v1(90.55,33.91) 90.7,34.06 P3.H21 ; 37.51,65.7 38.4,64.82 ; 38.4,64.82 39.29,63.93 ; 38.4,64.82 37.51,63.93 ; 38.4,64.82 39.29,65.7 ; v1(80.25,16.81) 80.25,16.62 79.62,15.99 R136.2 ; 5.13,4.11 P7.12 ; P7.12 6.9,2.34 ; P7.12 6.9,4.11 ; P7.12 5.13,2.34 ; TP3.1 51.18,64.42 ; TP3.1 49.5,64.42 ; TP3.1 51.18,66.1 ; TP3.1 49.5,66.1 ; P3.G1 v1(91.97,60.01) ; v1(93.6,20.44) 93.25,20.09 P3.G32 ; P8.4 37.43,5.17 ; P8.4 35.56,3.31 ; P8.4 37.43,3.31 ; P8.4 35.56,5.17 ; 27.35,65.7 28.24,64.82 ; 28.24,64.82 29.13,63.93 ; 28.24,64.82 27.35,63.93 ; 28.24,64.82 29.13,65.7 ; TP1.1 78.12,23.53 ; TP1.1 76.43,25.21 ; TP1.1 76.43,23.53 ; TP1.1 78.12,25.21 ; P12.1 32.22,47.59 ; P12.1 29.98,47.59 ; P12.1 32.22,45.35 ; P12.1 29.98,45.35 ; P2.2 45.97,38.99 ; P2.2 44.19,37.21 ; P2.2 45.97,37.21 ; P2.2 44.19,38.99 ; P3.G40 v1(91.97,9.38) ; 85.29,62.81 CLKIN.5 83.25,62.81 ; 8.64,37.21 P1.2 ; P1.2 10.41,37.21 ; P1.2 10.41,38.99 ; P1.2 8.64,38.99 ; 45.26,5.44 P11.2 ; P11.2 47.03,3.67 ; P11.2 47.03,5.44 ; P11.2 45.26,3.67 ; 83.25,67.91 CLKIN.4 ; CLKIN.4 85.29,65.87 ; CLKIN.4 83.25,65.87 ; CLKIN.4 85.29,67.91 ; 9.55,14.86 TP4.1 ; TP4.1 9.55,13.18 ; TP4.1 11.24,13.18 ; P3.D10 v1(95.68,48.03) ; 78.15,67.91 CLKIN.3 ; CLKIN.3 80.19,65.87 ; CLKIN.3 78.15,65.87 ; CLKIN.3 80.19,67.91 ; 6.19,55.18 TP2.1 ; TP2.1 7.87,55.18 ; TP2.1 7.87,53.5 ; TP2.1 6.19,53.5 ; P3.G23 v1(93.17,31.52) ; P3.D39 v1(96.87,10.65) ; P3.H30 v1(90.7,23.18) ; P3.D28 v1(96.87,24.62) ; v1(78.79,57.64) 78.79,56.95 R73.2 ; P1.6 10.41,27.05 ; P1.6 8.64,28.83 ; P1.6 8.64,27.05 ; P1.6 10.41,28.83 ; C69.2 76.99,51.37 ; v1(93.2,53.9) 93,53.9 P3.G5 ; v1(98.37,54.38) P3.C5 ; P3.D13 96.26,44.28 95.62,44.28 95.61,44.29 v1(95.55,44.29) ; P3.D37 v1(96.87,13.19) ; P5.1 18.18,45.48 ; P5.1 15.95,47.71 ; P5.1 15.95,45.48 ; P5.1 18.18,47.71 ; P3.G35 v1(91.97,15.73) ; P3.G8 v1(91.97,51.12) ; P3.D25 v1(96.87,28.43) ; v1(93.2,55.87) 92.99,55.65 ; 92.99,55.65 93.09,55.65 ; 92.99,55.65 P3.G4 ; P3.D22 v1(96.87,32.24) ; v1(93.2,35.29) 93.16,35.33 P3.G20 ; R124.2 35.49,38.23 ; P3.C21 v1(98.14,33.51) ; P3.C36 v1(98.14,14.46) ; P3.D16 v1(95.6,40.41) ; P3.C8 v1(98.34,51.32) ; P3.C33 v1(98.14,18.27) ; 45.97,28.83 P2.6 44.19,28.83 ; P3.C20 v1(98.14,35.88) ; R126.2 v1(39.2,38.23) ; P3.D6 v1(96.87,53.66) ; P3.C13 v1(98.31,44.22) ; v1(90.19,17.72) 91.24,18.77 P3.H33 ; v1(90.85,37.87) P3.H18 ; P3.C12 v1(98.31,45.49) ; P3.D3 v1(96.87,57.47) ; P3.D7 v1(96.87,52.39) ; P3.H12 v1(90.7,44.94) ; P3.G26 v1(93.06,27.16) ; P3.C16 v1(98.32,40.41) ; P3.C24 v1(98.14,29.7) ; v1(65.83,39.55) C99.2 ; P7.11 4.36,4.11 ; P7.11 2.59,4.11 ; P7.11 2.59,2.34 ; P7.11 4.36,2.34 ; P3.C32 v1(98.14,19.54) ; 80.19,62.81 CLKIN.2 78.15,62.81 ; P3.G14 v1(93.29,42.95) ; v1(98.37,55.65) P3.C4 ; P3.H9 v1(90.47,49.3) ; P3.C17 v1(98.32,39.14) ; P3.G29 v1(93.29,23.9) ; C70.2 v1(76.96,59.31) ; 79.67,14.27 v1(79.62,14.27) ; P3.G38 v1(91.97,11.92) ; P3.C28 v1(98.14,24.62) ; P3.C25 v1(98.14,28.43) ; P3.C1 v1(98.14,60.01) ; P3.H24 v1(90.16,30.25) ; P3.C29 v1(98.14,23.35) ; P3.H6 v1(90.7,52.56) ; P3.D19 v1(96.87,37.15) ; R38.1 71.8,41.96 ; P3.C9 v1(98.14,49.85) ; P3.D2 v1(96.87,58.74) ; P3.C40 v1(98.14,9.38) ; P3.G11 v1(93.29,46.76) ; P3.H36 v1(90.7,14.46)
  vias: v1(1.33,2.29) v1(1.52,48.01) v1(1.52,32.77) v1(1.52,17.53) v1(1.52,14.99) v1(1.52,12.45) v1(1.52,9.78) v1(1.52,7.24) v1(1.57,67.99) v1(1.57,66.09) v1(1.57,61.64) v1(1.57,59.1) v1(1.57,56.56) v1(1.57,54.02) v1(3.47,67.99) v1(4.06,48.01) v1(4.06,32.77) v1(4.06,17.53) v1(5.38,67.99) v1(6.6,60.96) v1(6.6,50.8) v1(6.6,48.01) v1(6.6,45.47) v1(6.6,42.93) v1(6.6,35.31) v1(6.6,32.77) v1(6.6,30.23) v1(6.6,22.61) v1(6.59,20.31) v1(7.42,17.27) v1(8.06,10.16) v1(8.25,12.83) v1(8.5,18.8) v1(8.55,67.99) v1(8.55,64.82) v1(8.76,5.46) v1(10.46,67.99) v1(10.46,62.91) v1(11.16,45.58) v1(11.68,32.77) v1(11.93,19.96) v1(12.06,11.3) v1(12.06,9.14) v1(12.36,67.99) v1(13.33,8.89) v1(13.71,11.24) v1(13.95,37.89) v1(13.95,22.65) v1(14.09,32.77) v1(14.21,57.01) v1(14.27,67.99) v1(16.17,67.99) v1(16.17,66.09) v1(16.76,32.77) v1(16.76,30.23) v1(16.81,4.18) v1(17.57,53.26) v1(17.56,52.29) v1(17.57,51.36) v1(17.77,67.94) v1(18.08,4.18) v1(18.46,53.26) v1(18.45,52.29) v1(18.46,51.36) v1(18.59,48.94) v1(19.29,42.28) v1(19.3,32.77) v1(19.3,30.23) v1(19.29,27.04) v1(19.35,4.18) v1(20.06,35.12) v1(20.06,19.88) v1(20.38,45.59) v1(20.49,56.63) v1(20.87,51.99) v1(20.87,23.67) v1(21.28,18.21) v1(21.65,38.02) v1(21.76,47.67) v1(21.89,39.16) v1(21.84,35.18) v1(21.84,32.77) v1(21.84,30.23) v1(22.72,38.59) v1(22.98,45.67) v1(23.41,47.8) v1(24.11,57.58) v1(24.05,14.84) v1(24.38,67.44) v1(24.38,43.18) v1(25,30.15) v1(25.13,21) v1(25.7,38.84) v1(26.92,40.39) v1(26.92,37.85) v1(26.92,27.69) v1(27.16,55.8) v1(27.8,27.93) v1(27.92,38.02) v1(28.7,67.56) v1(29.46,42.93) v1(29.46,40.39) v1(29.46,37.85) v1(29.46,27.69) v1(30.35,10.1) v1(30.35,9.33) v1(30.35,8.57) v1(30.53,13.07) v1(30.98,10.1) v1(30.98,9.33) v1(30.98,8.57) v1(31.61,53.13) v1(31.6,52.16) v1(31.61,51.23) v1(31.62,10.1) v1(31.62,9.33) v1(31.62,8.57) v1(32,40.39) v1(32,37.85) v1(32.3,20.18) v1(32.3,18.65) v1(32.49,53.13) v1(32.49,52.16) v1(32.49,51.23) v1(32.62,48.88) v1(33.27,67.69) v1(33.95,31.16) v1(34.15,34.72) v1(34.54,40.39) v1(34.72,58.41) v1(35.86,47.93) v1(36.05,19.16) v1(36.44,44.83) v1(36.57,67.69) v1(36.89,28.89) v1(36.89,28.38) v1(37.08,40.39) v1(37.4,28.89) v1(37.4,28.38) v1(37.51,17.19) v1(37.48,16.12) v1(37.51,15.1) v1(37.55,44.2) v1(37.59,36.51) v1(37.59,36) v1(38.02,54.79) v1(38.09,36.51) v1(38.09,36) v1(38.08,24.5) v1(38.3,16.12) v1(38.34,17.19) v1(38.34,15.1) v1(38.46,22.46) v1(39.62,40.39) v1(39.8,11.42) v1(40.05,29.96) v1(40.43,23.54) v1(40.62,19.29) v1(41.13,51.67) v1(42.08,35.16) v1(42.16,42.93) v1(42.16,40.39) v1(42.16,37.85) v1(42.16,27.69) v1(42.16,25.15) v1(42.34,44.44) v1(42.86,21.84) v1(43.35,56.88) v1(43.62,21.84) v1(43.73,33.7) v1(43.73,32.37) v1(44.38,21.84) v1(45.14,23.37) v1(45.14,22.61) v1(45.14,21.84) v1(45.32,53.13) v1(45.31,52.16) v1(45.32,51.23) v1(45.91,23.37) v1(45.91,22.61) v1(45.91,21.84) v1(46.1,57.66) v1(46.03,56.32) v1(46.21,53.13) v1(46.2,52.16) v1(46.21,51.23) v1(46.27,48.88) v1(46.67,23.37) v1(46.67,22.61) v1(46.67,21.84) v1(47.49,61.34) v1(48.07,58.8) v1(48.24,33.26) v1(48.31,18.97) v1(49.45,48.31) v1(49.52,13.49) v1(49.52,12.98) v1(50.03,13.49) v1(50.03,12.98) v1(50.21,43.55) v1(50.21,29.32) v1(50.15,14.78) v1(50.46,18.15) v1(50.91,8.24) v1(50.97,53.83) v1(51.05,46.04) v1(51.05,45.53) v1(51.05,31.75) v1(51.05,31.24) v1(51.56,46.04) v1(51.56,45.53) v1(51.56,31.75) v1(51.56,31.24) v1(51.54,3.29) v1(51.77,22.1) v1(51.77,21.59) v1(51.87,36.39) v1(51.87,35.88) v1(52.28,22.1) v1(52.28,21.59) v1(52.37,67.99) v1(52.38,36.39) v1(52.38,35.88) v1(53.14,62.1) v1(53.32,5.07) v1(53.97,67.06) v1(54.47,53.45) v1(54.6,61.09) v1(54.6,60.13) v1(54.59,57.71) v1(54.86,50.29) v1(54.86,48.64) v1(54.85,47.29) v1(55.35,57.71) v1(55.86,45.83) v1(56,21.72) v1(56,21.21) v1(55.94,15.33) v1(55.93,14.36) v1(55.94,13.42) v1(56.5,57.71) v1(56.51,21.72) v1(56.51,21.21) v1(56.82,14.36) v1(56.83,15.33) v1(56.83,13.42) v1(57.2,57.71) v1(57.45,42.34) v1(57.45,28.05) v1(57.74,60.97) v1(58.73,45.53) v1(58.92,60.95) v1(59.3,56.71) v1(59.3,55.44) v1(59.3,54.17) v1(59.42,10.27) v1(59.99,61.03) v1(60.12,18.34) v1(60.45,56.71) v1(60.45,54.17) v1(60.5,10.15) v1(61.15,11.39) v1(61.15,10.88) v1(61.27,47.31) v1(61.27,45.53) v1(61.51,49.2) v1(61.53,60.91) v1(61.59,56.71) v1(61.59,55.44) v1(61.59,54.17) v1(61.65,11.39) v1(61.65,10.88) v1(62.8,64.61) v1(62.73,60.88) v1(62.8,52.48) v1(63.11,43.56) v1(63.37,52.45) v1(63.62,14.88) v1(63.62,14.38) v1(63.8,67.99) v1(63.81,47.31) v1(63.81,45.53) v1(63.75,36.58) v1(63.99,25) v1(63.93,22.85) v1(63.99,21.13) v1(64.13,14.88) v1(64.13,14.38) v1(65.39,19.48) v1(65.7,67.99) v1(65.77,3.67) v1(66.04,59.25) v1(66.08,57.98) v1(66.07,52.9) v1(66.07,51.69) v1(66.2,56.91) v1(66.42,47.31) v1(66.35,45.53) v1(66.34,32.62) v1(66.72,54.03) v1(66.78,10.78) v1(66.86,56.88) v1(66.85,16.05) v1(66.85,15.35) v1(67.11,49.66) v1(67.18,52.39) v1(67.61,67.99) v1(67.56,42.93) v1(67.94,54.01) v1(67.94,45.78) v1(68.64,43.88) v1(68.64,42.74) v1(68.64,41.47) v1(68.96,52.39) v1(69.01,50.85) v1(69.02,49.66) v1(68.96,47.31) v1(69.51,67.99) v1(69.65,58.86) v1(70.02,41.7) v1(70.02,39.48) v1(70.04,43.88) v1(70.04,42.74) v1(70.28,17.89) v1(70.34,14.78) v1(70.66,47.29) v1(70.73,48.64) v1(71.05,67.5) v1(71.31,45.66) v1(71.31,43.88) v1(71.31,42.86) v1(71.31,41.66) v1(71.42,67.99) v1(71.36,37.96) v1(71.43,58.86) v1(71.43,57.34) v1(72.31,50.47) v1(72.26,27.75) v1(72.26,27.24) v1(72.25,13) v1(72.7,65.6) v1(72.63,48.63) v1(72.69,45.77) v1(72.7,43.88) v1(72.7,42.86) v1(72.7,41.66) v1(72.77,67.37) v1(72.75,47.29) v1(72.86,56.01) v1(72.86,54.87) v1(72.88,35.93) v1(72.94,38.02) v1(72.94,13) v1(73.15,64.96) v1(73.32,67.99) v1(73.26,42.28) v1(73.32,38.91) v1(73.46,43.37) v1(73.59,63.94) v1(73.9,48.63) v1(74,54.87) v1(74.02,47.17) v1(74.02,35.93) v1(73.97,25.65) v1(73.97,25.15) v1(74.1,67.25) v1(74.28,9.51) v1(74.48,25.65) v1(74.48,25.15) v1(74.59,11.35) v1(74.67,63.44) v1(74.72,33.26) v1(74.72,31.86) v1(74.86,66.42) v1(74.92,65.34) v1(75.1,35.42) v1(75.23,67.99) v1(75.23,50.47) v1(75.36,47.17) v1(75.74,45.01) v1(75.86,48.63) v1(75.94,65.21) v1(75.94,63.44) v1(75.99,33.26) v1(75.99,31.86) v1(76.12,53.58) v1(76.21,44.47) v1(76.37,35.42) v1(76.45,56.9) v1(77.01,45.77) v1(77.21,65.21) v1(77.2,50.47) v1(77.2,33.26) v1(77.2,31.86) v1(77.45,35.42) v1(77.45,13.32) v1(77.71,48.63) v1(78.15,41.01) v1(78.21,39.42) v1(78.21,37.96) v1(78.21,36.82) v1(78.15,34.02) v1(78.28,33.26) v1(78.4,42.47) v1(78.48,65.21) v1(78.48,63.44) v1(78.6,50.47) v1(78.91,30.27) v1(78.93,45.91) v1(79.02,4.89) v1(79.42,10.46) v1(79.67,54.07) v1(79.75,65.21) v1(79.75,63.44) v1(80.37,54.09) v1(80.94,54.47) v1(81.07,37.7) v1(81.15,47.5) v1(81.14,34.08) v1(81.71,49.26) v1(81.64,31.61) v1(81.71,3.22) v1(81.77,39.36) v1(82.04,61.98) v1(82.21,67.99) v1(82.15,43.1) v1(82.28,31.61) v1(82.42,47.82) v1(82.34,26.02) v1(82.34,22.34) v1(82.6,43.42) v1(82.6,39.67) v1(82.6,35.99) v1(82.72,8.11) v1(82.79,20.94) v1(83.12,48.58) v1(83.18,54.29) v1(83.18,46.55) v1(83.17,31.61) v1(83.61,6.53) v1(83.93,13.32) v1(84.06,39.23) v1(84.04,35.67) v1(84.2,54.29) v1(84.56,45.56) v1(84.64,23.3) v1(84.64,22.54) v1(84.64,21.78) v1(84.82,48.18) v1(84.75,29.58) v1(85.07,40.63) v1(85.07,14.21) v1(85.31,35.04) v1(85.28,23.3) v1(85.28,22.54) v1(85.28,21.78) v1(85.39,6.14) v1(85.91,23.3) v1(85.91,22.54) v1(85.91,21.78) v1(85.97,67.69) v1(85.97,65.79) v1(85.97,63.88) v1(86.04,61.66) v1(86.53,55.17) v1(86.68,57.95) v1(86.79,47.29) v1(87.12,38.29) v1(87.8,47.99) v1(87.88,67.69) v1(87.88,63.88) v1(87.87,62.53) v1(87.88,0.95) v1(88.12,60.82) v1(88.26,44.7) v1(88.5,58.02) v1(88.51,56.52) v1(88.44,34.47) v1(88.88,34.97) v1(89.2,48) v1(89.15,0.95) v1(89.9,46.47) v1(89.9,39.1) v1(90.09,20.24) v1(90.15,28.88) v1(90.41,30.97) v1(90.42,0.95) v1(91.87,56.18) v1(91.93,52.44) v1(93.26,33.39) v1(93.58,29.7) v1(93.9,57.64) v1(93.9,33.96) v1(94.03,39.23) v1(94.6,32.5) v1(94.66,48.75) v1(94.91,57.39) v1(94.98,42.21) v1(95.3,52.18) v1(95.3,50.79) v1(95.3,31.42) v1(95.55,33.51) v1(95.69,4.76) v1(95.69,2.86) v1(95.69,0.95) v1(95.8,56.25) v1(96.13,67.69) v1(96.13,65.15) v1(96.71,62.17) v1(97.01,51.23) v1(96.96,4.76) v1(96.96,2.86) v1(96.96,0.95) v1(97.07,16.88) v1(97.59,62.17) v1(98.23,4.76) v1(98.23,2.86) v1(98.23,0.95) v1(98.41,42.97) v1(98.85,33.01) v1(99.17,37.07) v1(99.31,67.69) v1(99.31,65.15) v1(99.5,4.76) v1(99.5,2.86) v1(99.5,0.95) v1(99.99,37.7) v1(99.99,28.94) v1(99.94,25.15) v1(99.94,22.61) v1(99.94,20.07) v1(99.94,17.53) v1(99.94,14.99) v1(99.94,12.45) v1(100.77,4.76) v1(100.77,2.86) v1(100.77,0.95) v1(101.85,67.69) v1(102.04,9.84) v1(102.04,7.3) v1(102.04,4.76) v1(102.04,2.86) v1(102.04,0.95) v1(103.31,61.53) v1(103.31,58.99) v1(103.31,56.45) v1(103.31,53.91) v1(103.31,51.37) v1(103.31,48.83) v1(103.31,46.29) v1(103.31,43.75) v1(103.31,41.21) v1(103.31,37.78) v1(103.31,35.24) v1(103.31,32.7) v1(103.31,30.16) v1(103.31,27.62) v1(103.31,25.08) v1(103.31,22.54) v1(103.31,20) v1(103.31,17.46) v1(103.31,14.92) v1(103.31,12.38) v1(103.31,9.84) v1(103.31,7.3) v1(103.31,4.76) v1(103.31,2.86) v1(103.31,0.95) v2(67.72,34.95) v2(67.72,34.3) v2(68.37,34.3) v2(68.37,33.66) v2(68.37,33.01) v2(69.02,34.3) v2(69.02,33.66) v2(69.02,33.01) v2(69.67,34.3) v2(69.67,33.66) v2(69.67,33.01) v2(69.67,32.36) v2(69.67,31.71) v2(70.32,34.95) v2(70.32,32.36) v3(0.51,44.97) v3(0.51,44.05) v3(0.51,43.14) v3(0.51,37.6) v3(0.51,36.69) v3(0.51,35.77) v3(0.51,30.27) v3(0.51,29.35) v3(0.51,28.44) v3(0.51,22.9) v3(0.51,21.99) v3(0.51,21.07) v3(1.58,44.97) v3(1.58,44.05) v3(1.58,43.14) v3(1.58,37.6) v3(1.58,36.69) v3(1.58,35.77) v3(1.58,30.27) v3(1.58,29.35) v3(1.58,28.44) v3(1.58,22.9) v3(1.58,21.99) v3(1.58,21.07) v3(2.64,44.97) v3(2.64,44.05) v3(2.64,43.14) v3(2.64,37.6) v3(2.64,36.69) v3(2.64,35.77) v3(2.64,30.27) v3(2.64,29.35) v3(2.64,28.44) v3(2.64,22.9) v3(2.64,21.99) v3(2.64,21.07)
AVDD11: length 25.5
  TOP w0.254: U8.A2 U8.A1
  TOP w0.305: v1(75.29,23.61) 78.22,20.68 A2.3
  BOTTOM w0.305: v1(63.93,28.5) 63.93,27.42 66.72,24.62 73.63,24.62 73.72,24.54 74.36,24.54 v1(75.29,23.61)
  vias: v1(65.51,37.27) v1(65.51,36.56) v1(65.51,35.86) v1(66.23,37.27)
DVDD11: length 0.1
  TOP w0.203: U8.A3 68.37,35.73
  vias: v1(67.84,37.16) v1(67.83,36.65) v1(70.38,40.65) v1(70.37,40.14)
V11_OK: length 16.8
  TOP w0.203: v1(70.86,8.68) 70.86,7.86 R47.2 70.86,6.47 U24.1 ; A2.4 v1(76.32,14.98) ; A3.4 v1(80.32,14.98)
  BOTTOM w0.203: v1(80.32,14.98) v1(76.32,14.98) 75.42,14.08 75.42,13.25 v1(70.86,8.68)
VDD_REFBUF: length 3
  TOP w0.508: U39.6 70.72,24.87 70.72,24.87 R1.1 C9.1
VDDAFE_U1: length 1.4
  TOP w0.381: C88.1 19.32,38.02
  TOP w0.635: 19.32,38.02 U1.6
VDDAFE_U2: length 3
  TOP w0.381: 19.32,22.78 C90.1 19.95,22.21
  TOP w0.635: 19.32,22.78 U2.6 ; R28.1 20.1,21.71 19.95,21.86 19.95,22.21
VDDCR11: length 10
  TOP w0.254: R23.2 21.66,56.62 21.46,56.82 v1(21.46,57.4)
  TOP w0.508: VDD_11.1 17.52,57.4 v1(21.46,57.4)
  BOTTOM w0.508: v1(21.46,57.4) 20.75,57.4 20.68,57.34 18.78,57.34 18.73,57.39 VDD_11.1
  vias: v1(21.46,56.71) v1(22.09,57.4) v1(22.09,56.71) v1(30.47,58.04) v1(30.47,57.34) v1(31.11,58.04) v1(31.11,57.34)
VDDIO11: length 13
  TOP w0.254: U5.6 C84.1 v1(83.93,27.93) ; U6.6 C1.1 89.3,47.29 v1(89.9,47.29) ; U7.6 C85.1 84.6,38.49 v1(84.08,38.49) ; v1(89.74,36.59) C59.1 U4.6
  TOP w0.508: R83.2 43.07,58.95 44.18,60.06 45.64,60.06 IOVDD.1
  vias: v1(40.83,58.1) v1(40.83,57.4) v1(41.46,58.1) v1(41.46,57.4) v1(50.41,55.82) v1(50.41,55.12) v1(51.05,55.82) v1(51.05,55.12) v1(79.91,40.21) v1(79.91,33.38) v1(80.29,44.41) v1(80.29,43.9) v1(80.29,37.05) v1(80.29,36.55) v1(80.29,29.19) v1(80.29,28.68) v1(80.29,25.51) v1(80.29,25) v1(80.29,21.83) v1(80.29,21.33) v1(80.42,40.21) v1(80.42,33.38)
VDDLDO: length 5.3
  L3_PRIMARY_POWER w0.508: 45.15,45.63 P6.2 45.15,47.31 ; 52.2,59.28 VDDLDO.1 52.2,60.96
  BOTTOM w0.508: C99.1 v1(67.86,39.55)
  vias: v2(68.37,34.95)
VINN: length 15.9
  TOP w0.203: R106.1 R6.1
  TOP w0.508: R6.1 P1.7 7.26,25.4 R3.1 INM.1
  BOTTOM w0.635: P1.7 TINM.1
VINP: length 18.2
  TOP w0.203: R52.1 R4.1
  TOP w0.508: R4.1 P1.1 9.25,40.37 R2.1 INP.1
  BOTTOM w0.635: P1.1 TINP.1
VSS_REFBUF: length 1.6
  TOP w0.508: U39.2 R152.1
VSSAFE: length 17.7
  TOP w0.635: v1(20.64,4.18) 20.64,5.26 S1.4A
  L3_PRIMARY_POWER w0.508: v1(20.64,4.18) 20.64,11.14 ; VSS2V5.1 27.75,17.4 ; VSS2V5.1 26.06,15.72 ; VSS2V5.1 26.06,17.4 ; VSS2V5.1 27.75,15.72
  BOTTOM w0.508: JP3.1 v1(34.49,39.23) ; JP19.1 12.06,37.4 v1(12.13,37.47) ; JP25.2 30.02,22.4 v1(29.07,22.4) ; JP20.3 v1(12.06,28.58) ; JP5.1 v1(38.2,39.23)
  vias: v1(20.06,44.05) v1(20.06,43.41) v1(20.06,28.81) v1(20.06,28.17) v1(20.7,44.05) v1(20.7,43.41) v1(20.7,28.81) v1(20.7,28.17) v1(35.3,33.46) v1(35.3,32.64) v1(35.68,39.75) v1(35.68,39.24) v1(36.19,39.75) v1(36.19,39.24) v1(36.19,33.46) v1(36.19,32.64) v1(50.92,34.23) v1(50.92,33.72) v1(50.93,19.94) v1(50.93,19.43) v1(51.43,34.23) v1(51.43,33.72) v1(51.44,19.94) v1(51.44,19.43) v1(56.13,44.01) v1(56.13,43.5) v1(56.13,29.78) v1(56.13,29.27) v1(56.64,44.01) v1(56.64,43.5) v1(56.64,29.78) v1(56.64,29.27)
VSSAFE_U1: length 1.7
  TOP w0.305: 17.59,41.5 17.59,42.26 C89.2
  TOP w0.635: U1.2 17.59,41.5
VSSAFE_U2: length 2.7
  TOP w0.305: C91.2 17.59,27 17.59,26.26
  TOP w0.508: 17.55,27.54 C91.2 17.02,27.04
  TOP w0.635: 17.59,26.26 U2.2
AD9508_RESET_N: length 15.4
  TOP w0.203: U9.4 79.67,45.86 79.67,47.86 78.02,49.52 72.44,49.52 71.74,50.21 v1(71.74,52.01)
  BOTTOM w0.203: U20.18 72.25,53.01 71.74,52.5 v1(71.74,52.01)
AD9508_S4: length 3.4
  BOTTOM w0.203: R73.1 R72.2 77.5,55.69 U20.9
AD9508_S5: length 3.4
  BOTTOM w0.203: R75.1 R74.2 77.5,55.19 U20.10
AD9508_SYNC: length 60.7
  TOP w0.178: v1(98.14,47.48) 98.14,48.55 U29.2
  BOTTOM w0.178: U20.20 70.81,54.69 69.59,53.47 69.59,51.22 71.58,49.23 79.99,49.23 81.93,51.17 86.41,51.17 89.07,53.83 89.07,59.39 90.74,61.06 91.84,61.06 93.49,59.41 95.35,59.41 96.58,60.64 98.42,60.64 100.2,58.86 100.2,48.89 98.79,47.48 v1(98.14,47.48) P3.C10
ADCIN+: length 5.7
  TOP w0.127: R70.2 R32.1 59.97,33.81 59.4,33.24 58.85,33.24 58.72,33.37 v1(58.72,33.83)
  BOTTOM w0.127: v1(58.72,33.83) 58.72,33.44 58.87,33.28 59.44,33.28 59.97,33.81 R32.1
ADCIN-: length 5.8
  TOP w0.127: R76.2 R88.1 59.97,32.52 59.53,32.96 58.85,32.96 58.72,32.83 v1(58.72,32.37)
  BOTTOM w0.127: R88.1 59.97,32.52 59.48,33.01 58.85,33.01 58.72,32.88 v1(58.72,32.37)
ADF435X_LOCK: length 89
  TOP w0.178: v1(54.41,54.37) 55.06,54.37 R123.2
  BOTTOM w0.178: P3.C23 98.01,31.94 99.63,31.94 102.05,34.37 102.05,59.87 97.94,63.98 93.77,63.98 93.47,63.68 90.83,63.68 89,61.85 87.18,61.85 85.75,60.41 78.39,60.41 77.04,61.77 57.64,61.77 55.93,60.06 55.93,55.69 54.99,54.76 54.8,54.76 v1(54.41,54.37)
AUXIN+: length 7.2
  BOTTOM w0.127: v2(67.72,33.66) 67.27,33.66 67.08,33.47 64.82,33.47 C39.2 64.09,33.39 63.8,33.39 63.19,34 C38.2 63.01,34 62.42,33.4 62.14,33.4 61.67,33.87 R31.2
AUXIN-: length 7.5
  BOTTOM w0.127: v2(67.72,33.01) 67.27,33.01 67.08,33.19 64.97,33.19 C40.1 64.11,33.11 63.81,33.11 C38.1 62.38,33.12 62.2,33.12 61.67,32.58 R89.2
CLK25M: length 13.2
  TOP w0.178: U30.29 54.06,55.19 53.72,55.53 53.72,61.4 55.23,62.91 55.23,63.13 Y1.3
CLK_N: length 73.7
  TOP w0.127: v1(71.55,38.83) 71.89,38.5 71.89,35.55 71.76,35.42 71.52,35.42 71.34,35.6 U8.A7
  L3_PRIMARY_POWER w0.127: v1(72.52,51.25) 72.86,50.91 72.86,49.67 73.38,49.15 80.83,49.15 81.96,50.28 81.96,52.37 83.01,53.43 84.67,53.43 85.61,54.37 86.89,54.37 88.17,53.09 93.55,53.09 94.04,52.59 94.04,51.55 v1(93.71,51.22) 94.04,50.88 94.04,50.62 93.92,50.49 91.81,50.49 90.35,51.95 85.22,51.95 81.7,48.43 80.56,48.43 80.23,48.09 72.42,48.09 71.89,47.56 71.89,39.17 v1(71.55,38.83)
  BOTTOM w0.127: v1(93.71,51.22) 94.04,50.88 94.04,50.09 94.34,49.8 95.83,49.8 P3.D9 ; U20.17 72.75,52.66 72.86,52.55 72.86,51.59 v1(72.52,51.25)
CLK_P: length 73.7
  TOP w0.127: U8.B7 71.34,34.95 71.52,35.14 71.88,35.14 72.17,35.43 72.17,38.5 v1(72.5,38.83)
  L3_PRIMARY_POWER w0.127: v1(73.47,51.25) 73.14,50.91 73.14,49.78 73.49,49.43 80.72,49.43 81.68,50.39 81.68,52.49 82.9,53.71 84.55,53.71 85.49,54.65 87,54.65 88.28,53.37 93.67,53.37 94.32,52.71 94.32,51.55 v1(94.66,51.22) 94.32,50.88 94.32,50.5 94.03,50.21 91.69,50.21 90.23,51.67 85.34,51.67 81.81,48.15 80.68,48.15 80.35,47.81 72.54,47.81 72.17,47.44 72.17,39.17 v1(72.5,38.83)
  BOTTOM w0.127: v1(94.66,51.22) 94.32,50.88 94.32,50.2 94.45,50.08 95.83,50.08 P3.D8 ; U20.16 73.25,52.66 73.14,52.55 73.14,51.59 v1(73.47,51.25)
CLK_PWR_SRC: length 13.5
  TOP w0.508: JP23.2 87.25,49.85 v1(86.04,49.85) C142.1 U32.1 ; v1(86.04,55.69) C141.1 U31.1
  L5_SECONDARY_POWER w0.508: v1(86.04,55.69) 86.04,55.69 85.26,54.91 85.26,50.62 v1(86.04,49.85)
CLK_SRCM: length 6.5
  TOP w0.127: C138.2 67.02,55.58 67.29,55.58 v1(67.62,55.92) 68.24,55.92 R68.2
  BOTTOM w0.127: U20.22 69.94,55.69 R69.1 69.33,55.58 67.96,55.58 v1(67.62,55.92)
CLK_SRCP: length 6.5
  TOP w0.127: C137.2 67.02,55.3 67.29,55.3 v1(67.62,54.97) 68.24,54.97 R65.2
  BOTTOM w0.127: v1(67.62,54.97) 67.95,55.3 69.33,55.3 R69.2 69.94,55.19 U20.21
CLKCOM: length 2.6
  TOP w0.203: U30.23 59.2,58.92 C123.1 58.84,59.27 C121.1
CLKIN_AUX: length 5.6
  TOP w0.178: CLKIN.1 R62.1 C65.1
CMSRC: length 25.8
  TOP w0.203: U8.G2 67.72,30.96 67.17,30.4
  TOP w0.305: JP8.2 62.55,10.19 62.55,24.52 67.17,29.13 67.17,30.4
CNV_N: length 73.3
  TOP w0.127: R40.1 95.06,55.36 94.75,55.68 94.75,55.88 v1(95.09,56.22) ; U8.A5 69.67,35.97 69.48,36.16 69.48,37.74 71.99,40.24 72.55,40.24 v1(72.89,39.9)
  L3_PRIMARY_POWER w0.127: v1(76.36,52.49) 76.69,52.83 76.69,53.98 77.92,55.21 80.46,55.21 82.66,57.4 90.2,57.4 90.6,57 92.26,57 92.53,56.73 93.22,56.73 93.59,57.1 94.42,57.1 94.71,56.81 94.71,56.6 v1(95.09,56.22) 94.84,55.97 94.84,55.79 96.1,54.54 96.1,50.38 94.99,49.28 91.23,49.28 90.12,50.39 85.63,50.39 84.96,49.72 84.96,49.13 82.36,46.54 82.36,45.9 81.42,44.96 76.68,44.96 75.99,45.64 74.7,45.64 74.57,45.51 74.57,43.08 74.11,42.62 74.11,40.62 73.71,40.22 73.21,40.22 v1(72.89,39.9)
  BOTTOM w0.127: U20.12 76.27,54.19 76.39,54.3 76.56,54.3 76.69,54.17 76.69,52.83 v1(76.36,52.49) ; RTCNV.2 72.89,39.87 R38.2
CNV_P: length 71.9
  TOP w0.127: v1(94.13,56.22) 94.47,55.88 94.47,55.68 94.16,55.36 R39.1 ; U8.A4 69.02,35.97 69.2,36.16 69.2,37.85 71.87,40.52 72.59,40.52 v1(72.89,40.83)
  L3_PRIMARY_POWER w0.127: v1(72.89,40.83) 73.23,40.5 73.59,40.5 73.83,40.74 73.83,42.73 74.29,43.19 74.29,45.63 74.58,45.92 76.11,45.92 76.79,45.24 81.3,45.24 82.09,46.02 82.09,46.66 84.68,49.25 84.68,49.83 85.51,50.67 90.23,50.67 91.35,49.56 94.88,49.56 95.82,50.49 95.82,54.42 94.56,55.68 94.56,55.79 v1(94.13,56.22) 94.43,56.51 94.43,56.69 94.3,56.82 93.71,56.82 93.34,56.45 92.41,56.45 92.14,56.72 90.49,56.72 90.08,57.12 82.77,57.12 80.58,54.93 78.04,54.93 76.97,53.86 76.97,52.83 v1(77.31,52.49)
  BOTTOM w0.127: v1(77.31,52.49) 76.97,52.83 76.97,54.29 76.68,54.58 76.39,54.58 76.27,54.69 U20.11
CPO: length 2.8
  TOP w0.203: R120.2 C125.1 62.26,51.56 61.7,52.13 U30.7
CS1_0: length 59.7
  L3_PRIMARY_POWER w0.203: v1(98.14,37.15) 98.14,38.53 97.76,38.91 97.76,40.64 99.31,42.19 99.31,47.18 100.36,48.24 100.36,56.42 97.1,59.69 93.37,59.69 91.61,61.45 87.2,61.45 86.44,60.69 86.09,60.69 85.08,59.69 77.46,59.69 75.69,61.47 71.06,61.47 70.86,61.26 70.86,58.65 71.2,58.31 71.66,58.31 71.84,58.48 v1(72.25,58.48)
  BOTTOM w0.203: P3.C19 v1(98.14,37.15) ; U20.1 v1(72.25,58.48)
CS1_1: length 89.5
  TOP w0.178: U30.3 59.7,52.02 59.11,51.44 v1(59.11,50.86)
  BOTTOM w0.178: v1(59.11,50.86) 57.91,52.07 57.91,58.17 59.23,59.48 62.47,59.48 63.26,58.69 66.49,58.69 68.89,61.09 76.96,61.09 78.04,60.01 86.01,60.01 87.46,61.46 89.16,61.46 90.98,63.27 93.63,63.27 93.94,63.58 97.71,63.58 101.66,59.63 101.66,48.42 101.65,48.4 101.65,34.68 99.32,32.35 98.04,32.35 P3.C22
CS_N_SRC: length 43.7
  BOTTOM w0.178: U11.3 83.1,23.47 R109.1 85.99,25.46 85.99,29.54 89.81,33.36 90.77,33.36 90.8,33.39 91.4,33.39 91.83,33.82 91.83,34.36 92.21,34.74 94.11,34.74 95.42,36.05 95.42,36.26 95.43,36.27 95.43,39.43 95.8,39.8 96.82,39.8 96.95,39.93 96.95,40.63 97.32,40.99 99.5,40.99 99.72,41.21 99.72,45.6 99.17,46.15 97.33,46.15 97.01,46.47 97.01,46.9 96.57,47.34 96.08,47.34 95.74,47 95.74,46.91 94.32,45.49 P3.G12
CSB: length 27
  TOP w0.178: v1(66.4,31.48) 66.63,31.71 U8.G1
  BOTTOM w0.178: R109.2 83.1,21.58 U11.4 82.23,20.89 81.9,20.56 80.18,20.56 79.67,21.07 79.67,24.03 79.23,24.48 79.23,26.15 77.2,28.18 75.26,28.18 74.88,28.56 67.83,28.56 66.91,29.48 66.91,30.97 v1(66.4,31.48)
DA_N: length 65.9
  TOP w0.127: U8.D7 71.34,33.66 71.52,33.83 71.85,33.83 73.19,32.49 73.57,32.49 v1(73.97,32.09)
  L3_PRIMARY_POWER w0.127: v1(73.97,32.09) 74.31,32.42 77.83,32.42 78.39,31.86 81.02,31.86 81.34,32.18 85.61,32.18 v2(86.55,31.24) 87.59,32.29 87.87,32.29 88.16,32.58 88.16,33.25 86.47,34.94 86.47,35.93 86.72,36.18 88.42,36.18 90.11,34.49 94.26,34.49 96.22,36.46 96.22,39.05 95.16,40.12 92.69,40.12 92.57,40.24 92.57,41.21 92.69,41.34 96.13,41.34 96.78,41.98 96.78,45.12 96.01,45.9 89.26,45.9 88.67,46.49 88.67,48.41 v1(89,48.75)
  BOTTOM w0.127: v1(89,48.75) 88.67,49.09 88.67,49.62 90.12,51.07 91.12,51.07 91.24,50.94 P3.H8
